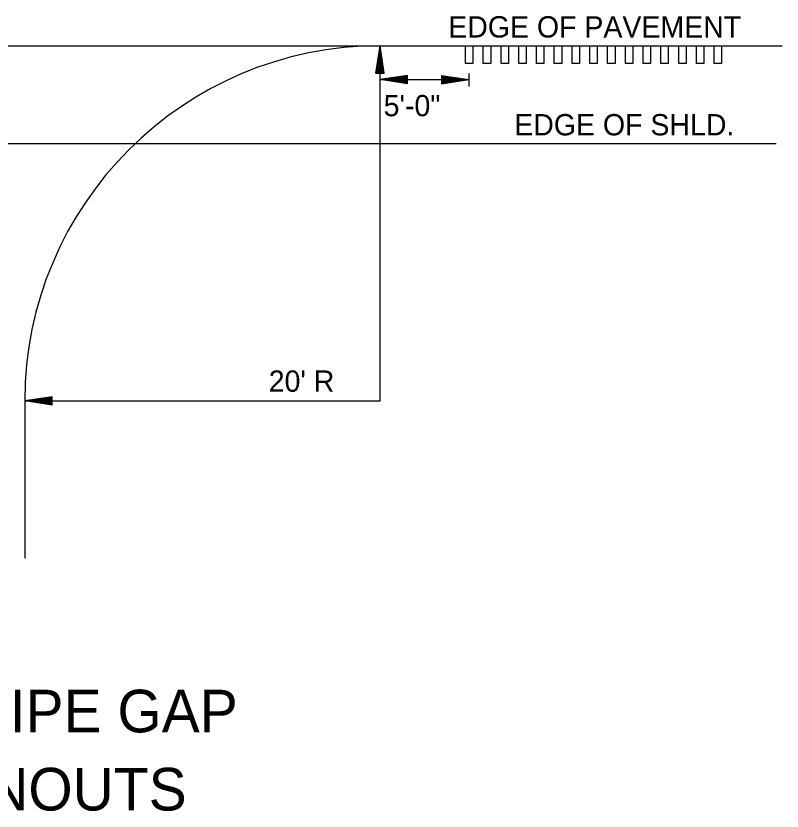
# Model space of a CAD drawing. Extents: x 438659 to 573674, y 10724 to 98600.
# Drawn here: x 533589 to 538766, y 24066 to 29440 of the extents above; entities that cross this region are included whole.
import ezdxf

# ---------------------------------------------------------------- set-up
doc = ezdxf.new("R2010")
doc.units = 0
doc.layers.add('Dimensions', color=7, linetype='Continuous')
doc.layers.add('T_Vehicle Path Rt', color=7, linetype='Continuous')

msp = doc.modelspace()

# ---------------------------------------------------------------- linework, layer by layer
at = {"layer": 'Dimensions'}
for p, q in [((536021.9, 29052.2), (536049.7, 29238.1)), ((536021.9, 29052.2), (536049.7, 29238.1)), ((536077.6, 29052.2), (536049.7, 29238.1)), ((536077.6, 29052.2), (536049.7, 29238.1)), ((536026.5, 29052.2), (536049.7, 29207)), ((536026.5, 29052.2), (536049.7, 29207)), ((536073, 29052.2), (536049.7, 29207)), ((536073, 29052.2), (536049.7, 29207)), ((536031.2, 29052.2), (536049.7, 29175)), ((536031.2, 29052.2), (536049.7, 29175)), ((536035.9, 29052.2), (536049.7, 29144.1)), ((536035.9, 29052.2), (536049.7, 29144.1)), ((536068.2, 29052.2), (536049.7, 29175)), ((536068.2, 29052.2), (536049.7, 29175)), ((536063.6, 29052.2), (536049.7, 29144.1)), ((536063.6, 29052.2), (536049.7, 29144.1)), ((536040.7, 29052.2), (536049.7, 29112.6)), ((536040.7, 29052.2), (536049.7, 29112.6)), ((536045.4, 29052.2), (536049.7, 29081.5)), ((536045.4, 29052.2), (536049.7, 29081.5)), ((536058.8, 29052.2), (536049.7, 29112.6)), ((536058.8, 29052.2), (536049.7, 29112.6)), ((536054.1, 29052.2), (536049.7, 29081.5)), ((536054.1, 29052.2), (536049.7, 29081.5)), ((536021.9, 29052.2), (536077.6, 29052.2)), ((536021.9, 29052.2), (536077.6, 29052.2)), ((536235.6, 29036.9), (536049.7, 29009)), ((536235.6, 29032.3), (536080.8, 29009)), ((536235.6, 29027.5), (536112.7, 29009)), ((536235.6, 29022.9), (536143.7, 29009)), ((536235.6, 29018.1), (536175.2, 29009)), ((536235.6, 28981.2), (536235.6, 29036.9)), ((536463.9, 29036.9), (536649.7, 29009)), ((536463.9, 29036.9), (536463.9, 28981.2)), ((536463.9, 29032.3), (536618.7, 29009)), ((536463.9, 29027.5), (536586.7, 29009)), ((536463.9, 29022.9), (536555.8, 29009)), ((536463.9, 29018.1), (536524.3, 29009)), ((536235.6, 28981.2), (536049.7, 29009)), ((536235.6, 28985.8), (536080.8, 29009)), ((536235.6, 28990.5), (536112.7, 29009)), ((536235.6, 28995.2), (536143.7, 29009)), ((536235.6, 29000), (536175.2, 29009)), ((536235.6, 29013.4), (536206.2, 29009)), ((536235.6, 29004.7), (536206.2, 29009)), ((536463.9, 29013.4), (536493.2, 29009)), ((536463.9, 28981.2), (536649.7, 29009)), ((536463.9, 28999.9), (536524.3, 29009)), ((536463.9, 28990.5), (536586.7, 29009)), ((536463.9, 28985.8), (536618.7, 29009)), ((536463.9, 28995.2), (536555.8, 29009)), ((536463.9, 29004.7), (536493.2, 29009)), ((533835.2, 26865.6), (533649.4, 26837.7)), ((533835.2, 26865.6), (533649.4, 26837.7)), ((533835.2, 26809.8), (533649.4, 26837.7)), ((533835.2, 26809.8), (533649.4, 26837.7)), ((533835.2, 26860.9), (533680.4, 26837.7)), ((533835.2, 26860.9), (533680.4, 26837.7)), ((533835.2, 26814.4), (533680.4, 26837.7)), ((533835.2, 26814.4), (533680.4, 26837.7)), ((533835.2, 26856.2), (533712.4, 26837.7)), ((533835.2, 26856.2), (533712.4, 26837.7)), ((533835.2, 26819.2), (533712.4, 26837.7)), ((533835.2, 26819.2), (533712.4, 26837.7)), ((533835.2, 26851.5), (533743.3, 26837.7)), ((533835.2, 26851.5), (533743.3, 26837.7)), ((533835.2, 26823.8), (533743.3, 26837.7)), ((533835.2, 26823.8), (533743.3, 26837.7)), ((533835.2, 26846.8), (533774.8, 26837.7)), ((533835.2, 26846.8), (533774.8, 26837.7)), ((533835.2, 26828.7), (533774.8, 26837.7)), ((533835.2, 26828.7), (533774.8, 26837.7)), ((533835.2, 26842), (533805.9, 26837.7)), ((533835.2, 26842), (533805.9, 26837.7)), ((533835.2, 26833.3), (533805.9, 26837.7)), ((533835.2, 26833.3), (533805.9, 26837.7)), ((533835.2, 26809.8), (533835.2, 26865.6)), ((533835.2, 26809.8), (533835.2, 26865.6))]:
    msp.add_line(p, q, dxfattribs=at)
at = {"layer": 'T_Vehicle Path Rt'}
for p, q in [((526444.3, 29238.1), (538765.9, 29238.1)), ((536049.7, 26837.7), (536049.7, 29238.1)), ((536649.7, 29050.3), (536649.7, 28961.6)), ((536049.7, 29009), (536649.7, 29009)), ((526404.5, 28576.7), (538726.1, 28576.7)), ((533649.4, 26837.7), (533649.4, 25774.8)), ((533649.4, 26837.7), (536049.7, 26837.7))]:
    msp.add_line(p, q, dxfattribs=at)
for points in [[(536627.1, 29117.8), (536627.1, 29237.8), (536677.1, 29237.8), (536677.1, 29117.8), (536627.1, 29117.8)], [(536747.1, 29117.8), (536747.1, 29237.8), (536797.1, 29237.8), (536797.1, 29117.8), (536747.1, 29117.8)], [(536867.1, 29117.8), (536867.1, 29237.8), (536917.1, 29237.8), (536917.1, 29117.8), (536867.1, 29117.8)], [(536987.1, 29117.8), (536987.1, 29237.8), (537037.1, 29237.8), (537037.1, 29117.8), (536987.1, 29117.8)], [(537107.1, 29117.8), (537107.1, 29237.8), (537157.1, 29237.8), (537157.1, 29117.8), (537107.1, 29117.8)], [(537227.1, 29117.8), (537227.1, 29237.8), (537277.1, 29237.8), (537277.1, 29117.8), (537227.1, 29117.8)], [(537347.1, 29117.8), (537347.1, 29237.8), (537397.1, 29237.8), (537397.1, 29117.8), (537347.1, 29117.8)], [(537467.1, 29117.8), (537467.1, 29237.8), (537517.1, 29237.8), (537517.1, 29117.8), (537467.1, 29117.8)], [(537587.1, 29117.8), (537587.1, 29237.8), (537637.1, 29237.8), (537637.1, 29117.8), (537587.1, 29117.8)], [(537707.1, 29117.8), (537707.1, 29237.8), (537757.1, 29237.8), (537757.1, 29117.8), (537707.1, 29117.8)], [(537827.1, 29117.8), (537827.1, 29237.8), (537877.1, 29237.8), (537877.1, 29117.8), (537827.1, 29117.8)], [(537947.1, 29117.8), (537947.1, 29237.8), (537997.1, 29237.8), (537997.1, 29117.8), (537947.1, 29117.8)], [(538067.2, 29117.8), (538067.2, 29237.8), (538117.1, 29237.8), (538117.1, 29117.8), (538067.2, 29117.8)], [(538187.2, 29117.8), (538187.2, 29237.8), (538237.1, 29237.8), (538237.1, 29117.8), (538187.2, 29117.8)], [(538307.2, 29117.8), (538307.2, 29237.8), (538357.2, 29237.8), (538357.2, 29117.8), (538307.2, 29117.8)]]:
    msp.add_lwpolyline(points, dxfattribs=at)
msp.add_arc((536049.7, 26837.7), 2400.4, 90, 180, dxfattribs=at)

# ---------------------------------------------------------------- texts
for s, height, p in [('EDGE OF PAVEMENT', 144.004, (536510.2, 29293.5)), ('5\'-0"', 144, (536074.1, 28761.5)), ('EDGE OF SHLD.', 144.004, (536956.2, 28632.2)), ("20' R", 144, (535297.6, 26899.6)), ('DETAIL FOR RUMBLE STRIPE GAP', 288.008, (528689.9, 24598.1)), ('AT DRIVEWAY TURNOUTS', 288.008, (529843.3, 24070.1))]:
    msp.add_text(s, height=height, dxfattribs=at).set_placement(p)

doc.saveas('drawing.dxf')
